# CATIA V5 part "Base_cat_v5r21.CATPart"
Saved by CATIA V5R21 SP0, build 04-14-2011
Part number: Base
Nomenclature: 1
Bounding box of the stored display mesh (mm): x -32 to 32, y 0 to 144, z 0 to 52
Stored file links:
  D:\CATIA V5R21 E-RESOURCES\CATIA-V5R21\catia-v5r21-Tut\c13-catia-v5r21-tut\c13-catia-v5r21-tut02\Bench Vice\Base_cat_v5r21.CATPart
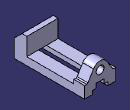
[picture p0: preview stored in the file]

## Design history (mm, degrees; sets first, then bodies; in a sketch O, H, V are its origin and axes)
Body1 (main body)
  Sketch1 on xy-plane, origin (0, 0, 0), H (1, 0, 0), V (0, 1, 0)
    point P1 (-32, 0)
    line L1 (-32, 0) -> (32, 0)
    line L2 (32, 0) -> (32, 144)
    line L3 (32, 144) -> (-32, 144)
    line L4 (-32, 144) -> (-32, 0)
    length L1 = 64
    length L2 = 144
    distance V L2 = 32
    coincidence: P1 H
    horizontal: L1 H, L3 H
    vertical: L2 V, L4 V
  Pad1: profile Sketch1, direction (0, 0, 1), length 16
  Sketch2 on face of Pad1, origin (32, 0, 0), H (0, 1, 0), V (0, 0, 1)
    point P1 (0, 16)
    line L1 (0, 16) -> (0, 36)
    point P2 (0, 36)
    line L2 (26, 52) -> (26, 16)
    line L3 (26, 16) -> (0, 16)
    reference projected line E1 (144, 16) -> (0, 16) from edge of Pad1
    line L4 (26, 52) -> (16, 52)
    point P5 (16, 52)
    line L5 (16, 52) -> (0, 36)
    length L2 = 36
    distance P5 P2 H = 16
    distance P5 P2 V = 16
    length L3 = 26
    coincidence: P1 V, E1 L3
    vertical: L1 V, L2 V
    horizontal: L3 H, L4 H
  Pad2: profile Sketch2, direction (-1, 0, 0), length 64
  Sketch3 on face of Pad1, origin (0, 144, 0), H (-1, 0, 0), V (0, 0, 1)
    line L1 (-32, 16) -> (-32, 24)
    point P2 (32, 24)
    line L2 (32, 24) -> (32, 16)
    line L3 (32, 16) -> (-32, 16)
    reference projected line E1 (32, 16) -> (-32, 16) from edge of Pad1
    line L4 (32, 24) -> (26, 24)
    point P4 (26, 24)
    line L5 (26, 24) -> (13.6777, 44.3018)
    point P5 (0, 52)
    line L6 (-13.6777, 44.3018) -> (-26, 24)
    point P6 (-26, 24)
    line L7 (-26, 24) -> (-32, 24)
    reference projected line E2 (32, 52) -> (-32, 52) from edge of Pad2
    reference projected line E3 (32, 16) -> (32, 52) from edge of Pad2
    reference projected line E4 (-32, 0) -> (-32, 16) from edge of Pad1
    arc A1 centre (0, 36) radius 16 from (13.6777, 44.3018) to (-13.6777, 44.3018) ccw
    point P8 (0, 36)
    reference projected line E5 (32, 52) -> (-32, 52) from edge of Pad2
    circle A2 centre (0, 36) radius 8
    distance H P2 = 24
    distance P6 P4 = 52
    distance P6 V = 26
    radius A1 = 16
    radius A2 = 8
    vertical: L1 V, L2 V
    horizontal: L3 H, L4 H, L7 H
    coincidence: L3 E1, P5 V, P6 L4, P5 E2, L2 E3, L1 E4, P8 V
    tangency: A1 E5, L6 A1, A1 L5
  Pad3: profile Sketch3, direction (0, -1, 0), length 22
  Fillet1: radius 3, on 2 edges
  Sketch4 on face of Pad1, origin (0, 144, 0), H (-1, 0, 0), V (0, 0, 1)
    point P1 (-16, 0)
    line L1 (-16, 0) -> (-16, 7)
    point P2 (-16, 7)
    line L2 (-16, 7) -> (-8, 7)
    point P3 (-8, 7)
    line L3 (-8, 7) -> (-8, 16)
    point P4 (-8, 16)
    line L4 (-8, 16) -> (0, 16)
    point P5 (0, 16)
    point P6 (16, 7)
    point P7 (16, 0)
    line L5 (16, 0) -> (16, 7)
    point P8 (8, 7)
    line L6 (16, 7) -> (8, 7)
    point P9 (8, 16)
    line L7 (8, 7) -> (8, 16)
    point P10 (0, 16)
    line L8 (8, 16) -> (0, 16)
    line L9 (-16, 0) -> (16, 0)
    point P11 (16, 0)
    distance L1 V = 16
    distance L3 V = 8
    distance H L4 = 16
    distance H L2 = 7
    coincidence: P1 H, P5 V, P7 P11, P5 P10
    vertical: L1 V, L3 V
    horizontal: L2 H, L4 H, L9 H
    symmetry: P2 P6 V, P1 P7 V, L1 L5 V, P3 P8 V, L2 L6 V, P4 P9 V, L3 L7 V, P5 P10 V, L4 L8 V
  Pocket1: profile Sketch4, direction (0, -1, 0), through (limit type 3)
  Sketch5 on face of Pad1, origin (0, 0, 0), H (1, 0, 0), V (0, -1, 0)
    circle A1 centre (22, -38) radius 3
    point P1 (22, -38)
    reference projected line E1 (32, 0) -> (-32, 0) from edge of Pad1
    radius A1 = 3
    distance P1 E1 = 38
    distance V P1 = 22
  Pocket2: profile Sketch5, direction (0, 0, 1), length 12
  RectPattern1: of Pocket2, direction 1 instances 2, spacing 70, along edge of Pad1, direction 2 instances 2, spacing 44, along edge of Pad1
